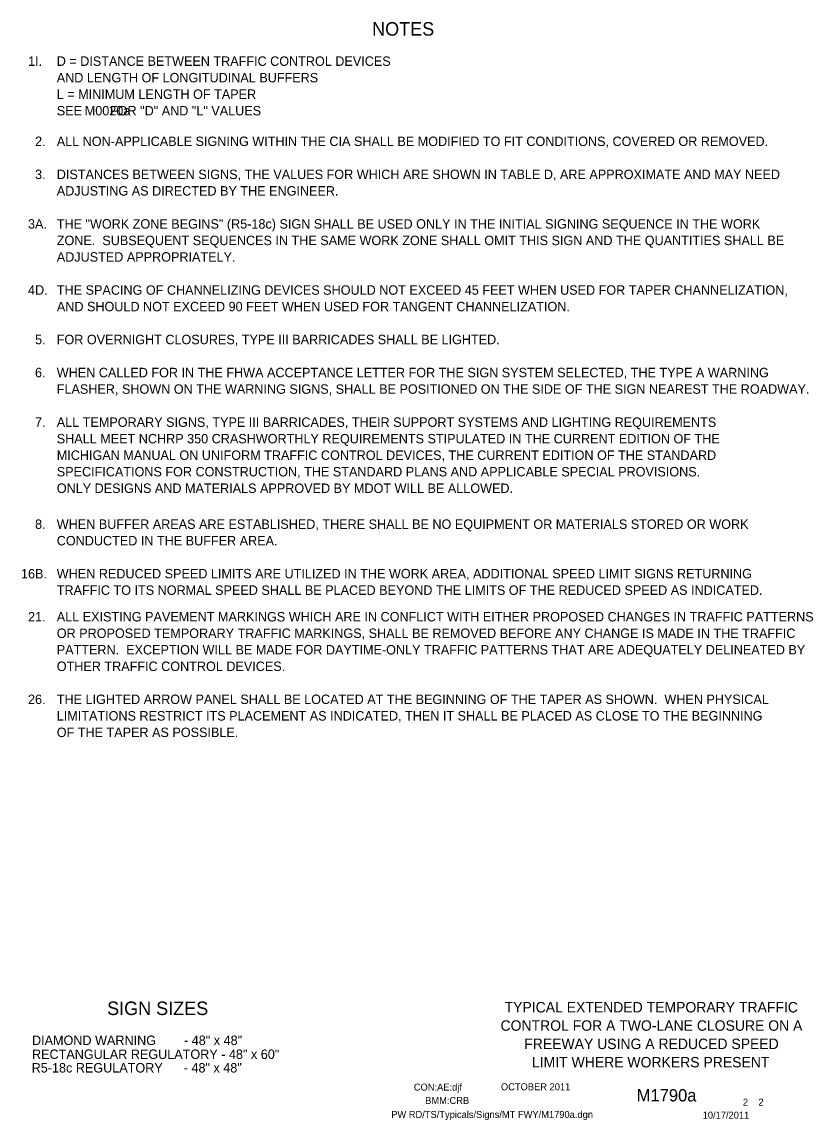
# Model space of a CAD drawing. Extents: x 16553 to 18475, y 5759 to 7026.
# Drawn here: x 17771 to 18475, y 5932 to 6909 of the extents above; entities that cross this region are included whole.
import ezdxf

# ---------------------------------------------------------------- set-up
doc = ezdxf.new("R2010")
doc.units = 0
for name, color, linetype in [('BORDER', 7, 'Continuous'), ('BORDER_SIGNAL_WO', 7, 'Continuous'), ('TYPICAL_TEXT_DIMEN_PR', 7, 'Continuous')]:
    doc.layers.add(name, color=color, linetype=linetype)

msp = doc.modelspace()

# ---------------------------------------------------------------- linework, layer by layer
at = {"layer": 'BORDER'}
msp.add_line((17909.25, 6035.02), (17909.25, 6035.02), dxfattribs=at)

# ---------------------------------------------------------------- texts
for s, p in [('TYPICAL EXTENDED TEMPORARY TRAFFIC', (18200.54, 6027.6)), ('CONTROL FOR A TWO-LANE CLOSURE ON A', (18196.92, 6011.3)), ('FREEWAY USING A REDUCED SPEED', (18218.02, 5995)), ('LIMIT WHERE WORKERS PRESENT', (18224.92, 5978.7))]:
    msp.add_text(s, height=9.3, dxfattribs=at).set_placement(p)
at = {"layer": 'BORDER_SIGNAL_WO'}
for s, height, p in [('CON:AE:djf  ', 6.2, (18119.69, 5958.06)), ('    OCTOBER 2011', 6.2, (18188.08, 5958.34)), ('BMM:CRB', 6.2, (18129.81, 5946.17)), ('    M1790a   ', 11, (18301.86, 5948.38)), (' 2    2 ', 6.2, (18410.45, 5944.7)), ('PW RD/TS/Typicals/Signs/MT FWY/M1790a.dgn      ', 6.2, (18099.55, 5933.71)), ('10/17/2011', 6.2, (18376.93, 5933.13))]:
    msp.add_text(s, height=height, dxfattribs=at).set_placement(p)
at = {"layer": 'TYPICAL_TEXT_DIMEN_PR'}
for s, height, p in [('NOTES', 12, (18082.55, 6897)), ('1I.', 8.4, (17776.19, 6870.11)), ('D = DISTANCE BETWEEN TRAFFIC CONTROL DEVICES', 8.4, (17801.7, 6870.11)), ('AND LENGTH OF LONGITUDINAL BUFFERS', 8.4, (17801.7, 6855.41)), ('L = MINIMUM LENGTH OF TAPER', 8.4, (17801.7, 6840.71)), ('SEE        FOR "D" AND "L" VALUES', 8.4, (17801.7, 6826.01)), ('M0020a', 8.4, (17826.62, 6826.01)), ('2.', 8.4, (17782.39, 6798.75)), ('ALL NON-APPLICABLE SIGNING WITHIN THE CIA SHALL BE MODIFIED TO FIT CONDITIONS, COVERED OR REMOVED.', 8.4, (17801.7, 6798.75)), ('3.', 8.4, (17782.39, 6769.35)), ('DISTANCES BETWEEN SIGNS, THE VALUES FOR WHICH ARE SHOWN IN TABLE D, ARE APPROXIMATE AND MAY NEED', 8.4, (17801.7, 6769.35)), ('ADJUSTING AS DIRECTED BY THE ENGINEER.', 8.4, (17801.7, 6754.65)), ('THE "WORK ZONE BEGINS" (R5-18c) SIGN SHALL BE USED ONLY IN THE INITIAL SIGNING SEQUENCE IN THE WORK', 8.4, (17801.7, 6725.24)), ('3A.', 8.4, (17776.09, 6725.24)), ('ZONE.  SUBSEQUENT SEQUENCES IN THE SAME WORK ZONE SHALL OMIT THIS SIGN AND THE QUANTITIES SHALL BE', 8.4, (17801.7, 6710.54)), ('ADJUSTED APPROPRIATELY.', 8.4, (17801.7, 6695.84)), ('4D.', 8.4, (17776.13, 6666.45)), ('THE SPACING OF CHANNELIZING DEVICES SHOULD NOT EXCEED 45 FEET WHEN USED FOR TAPER CHANNELIZATION,', 8.4, (17801.8, 6666.38)), ('AND SHOULD NOT EXCEED 90 FEET WHEN USED FOR TANGENT CHANNELIZATION.', 8.4, (17801.8, 6651.68)), ('5.', 8.4, (17782.39, 6622.35)), ('FOR OVERNIGHT CLOSURES, TYPE III BARRICADES SHALL BE LIGHTED.', 8.4, (17801.7, 6622.35)), ('6.', 8.4, (17782.34, 6592.95)), ('WHEN CALLED FOR IN THE FHWA ACCEPTANCE LETTER FOR THE SIGN SYSTEM SELECTED, THE TYPE A WARNING ', 8.4, (17801.7, 6592.95)), ('FLASHER, SHOWN ON THE WARNING SIGNS, SHALL BE POSITIONED ON THE SIDE OF THE SIGN NEAREST THE ROADWAY.', 8.4, (17801.7, 6578.25)), ('7.', 8.4, (17782.34, 6548.77)), ('ALL TEMPORARY SIGNS, TYPE III BARRICADES, THEIR SUPPORT SYSTEMS AND LIGHTING REQUIREMENTS', 8.4, (17801.7, 6548.79)), ('SHALL MEET NCHRP 350 CRASHWORTHLY REQUIREMENTS STIPULATED IN THE CURRENT EDITION OF THE', 8.4, (17801.7, 6534.09)), ('MICHIGAN MANUAL ON UNIFORM TRAFFIC CONTROL DEVICES, THE CURRENT EDITION OF THE STANDARD', 8.4, (17801.7, 6519.39)), ('SPECIFICATIONS FOR CONSTRUCTION, THE STANDARD PLANS AND APPLICABLE SPECIAL PROVISIONS.', 8.4, (17801.7, 6504.69)), ('ONLY DESIGNS AND MATERIALS APPROVED BY MDOT WILL BE ALLOWED.', 8.4, (17801.7, 6489.99)), ('8.', 8.4, (17782.39, 6458)), ('WHEN BUFFER AREAS ARE ESTABLISHED, THERE SHALL BE NO EQUIPMENT OR MATERIALS STORED OR WORK     ', 8.4, (17801.7, 6458)), ('CONDUCTED IN THE BUFFER AREA.', 8.4, (17801.7, 6443.3)), ('16B.', 8.4, (17769.84, 6413.9)), ('WHEN REDUCED SPEED LIMITS ARE UTILIZED IN THE WORK AREA, ADDITIONAL SPEED LIMIT SIGNS RETURNING', 8.4, (17801.7, 6413.96)), ('TRAFFIC TO ITS NORMAL SPEED SHALL BE PLACED BEYOND THE LIMITS OF THE REDUCED SPEED AS INDICATED.', 8.4, (17801.7, 6399.26)), ('21.', 8.4, (17776.14, 6375.61)), ('ALL EXISTING PAVEMENT MARKINGS WHICH ARE IN CONFLICT WITH EITHER PROPOSED CHANGES IN TRAFFIC PATTERNS', 8.4, (17801.7, 6375.61)), ('OR PROPOSED TEMPORARY TRAFFIC MARKINGS, SHALL BE REMOVED BEFORE ANY CHANGE IS MADE IN THE TRAFFIC', 8.4, (17801.7, 6360.91)), ('PATTERN.  EXCEPTION WILL BE MADE FOR DAYTIME-ONLY TRAFFIC PATTERNS THAT ARE ADEQUATELY DELINEATED BY', 8.4, (17801.7, 6346.21)), ('OTHER TRAFFIC CONTROL DEVICES.', 8.4, (17801.7, 6331.51)), ('26.', 8.4, (17776.09, 6302.11)), ('THE LIGHTED ARROW PANEL SHALL BE LOCATED AT THE BEGINNING OF THE TAPER AS SHOWN.  WHEN PHYSICAL', 8.4, (17801.7, 6302.11)), ('LIMITATIONS RESTRICT ITS PLACEMENT AS INDICATED, THEN IT SHALL BE PLACED AS CLOSE TO THE BEGINNING', 8.4, (17801.7, 6287.41)), ('OF THE TAPER AS POSSIBLE.', 8.4, (17801.7, 6272.71)), ('SIGN SIZES', 12, (17846.54, 6025.28)), ('DIAMOND WARNING        - 48" x 48"', 8.4, (17779.65, 5998.62)), ('RECTANGULAR REGULATORY - 48" x 60"', 8.4, (17779.65, 5986.22)), ('R5-18c REGULATORY      - 48" x 48"', 8.4, (17779.34, 5974.14))]:
    msp.add_text(s, height=height, dxfattribs=at).set_placement(p)

doc.saveas('drawing.dxf')
